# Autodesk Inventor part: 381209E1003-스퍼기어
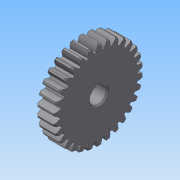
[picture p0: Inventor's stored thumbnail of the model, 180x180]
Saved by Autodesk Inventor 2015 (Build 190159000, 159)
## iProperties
Created: 2018-12
Part Number: 381209E1003-스퍼기어
Material: 일반
Document SubType Name: Modeling
Designer: user
Density: 1 g/cm^3
Appearance: 기본값
Author: user
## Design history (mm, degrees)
sketch "스케치1"
  geometry: L1 (0, 0)-(13, 0); L2 (0, 0)-(0, 12.5); L3 (0, 12.5)-(6, 12.5); L4 (6, 12.5)-(6, 22.5); L5 (6, 22.5)-(0, 22.5); L6 (0, 22.5)-(0, 27.5); L7 (0, 27.5)-(13, 27.5); L8 (13, 27.5)-(13, 0); L9 (0, 30)-(13, 30); L10 (0, 32)-(13, 32)
  constraints: 20 end point, 4 perpendicular, 3 horizontal, 2 point on line, 1 parallel, 1 vertical
  dimensions: "d0" = 13 distance of L1.start L1.end; "d1" = 25 diameter of L3 L1; "d2" = 45 diameter of L5 L1; "d3" = 6 distance between parallel lines of L4 L2; "d5" = 2 distance of L9.end L10.end; "d6" = 4.5 distance between parallel lines of L7 L10; "d7" = 60 diameter of L9 L1
revolve "회전1" sketch "스케치1" stored, may be unused: angle "d8" = 90 deg
sketch "스케치2"
  geometry: L1 (5.657, 2)-(7.8, 2); L2 (7.8, 2)-(7.8, -2); L3 (7.8, -2)-(5.657, -2); C1 r 12.5 at (0, 0) reference; A1 r 6 centre (0, 0) between (5.657, 2) and (5.657, -2)
  constraints: 6 end point, 2 perpendicular, 2 point on circle, 1 centre point, 1 coincident, 1 horizontal, 1 parallel
  dimensions: "d9" = 12 diameter of A1; "d10" = 4 distance of L1.end L2.end; "d11" = 1.8 distance edge to line of A1 L2
extrude "돌출1" cut sketch "스케치2" stored distance "d12" = 10; taper "d13" = 0 deg
sketch "스케치3"
  geometry: L1 (0, 0)-(32, 0); A1 r 27.5 centre (0, 0) between (27.422, 2.07) and (27.5, 0) reference; A2 r 32 centre (0, 0) between (31.995, -0.57) and (31.995, 0.57); A3 r 30 centre (0, 0) between (29.959, -1.57) and (29.959, 1.57); A4 r 9.292 centre (26.911, -7.208) between (31.995, 0.57) and (27.422, 2.07); A5 r 9.292 centre (26.911, 7.208) between (27.422, -2.07) and (31.995, -0.57); A6 r 27.5 centre (0, 0) between (27.422, -2.07) and (27.422, 2.07)
  constraints: 16 point on circle, 5 centre point, 3 symmetric about line, 2 end point, 1 horizontal, 1 point on line, 1 other
  dimensions: "d16" = 2 radial gap between concentric circles of A2 A3; "d17" = 4.5 radial gap between concentric circles of A2 A1; "d18" = 1 vertical distance of A2.end A3.end; "d19" = 0.5 vertical distance of A1.start A3.end; "d21" = 1.57 vertical distance of L1.end A3.end
extrude "돌출2" join sketch "스케치3" stored distance "d22" = 10; taper "d23" = 0 deg
chamfer "모따기1" distance "d24" = 1; stored, may be unused: second distance "d25" = 2, angle "d26" = 45 deg
fillet "모깎기1" dims "d30" = 3
fillet "모깎기2" dims "d31" = 3
chamfer "모따기2" distance "d32" = 1; stored, may be unused: second distance "d33" = 2, angle "d34" = 45 deg
node "솔리드1"
pattern_circular "원형 패턴1" dims angle "d28" = 360 deg
